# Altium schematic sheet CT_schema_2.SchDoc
size 461 x 297 mm
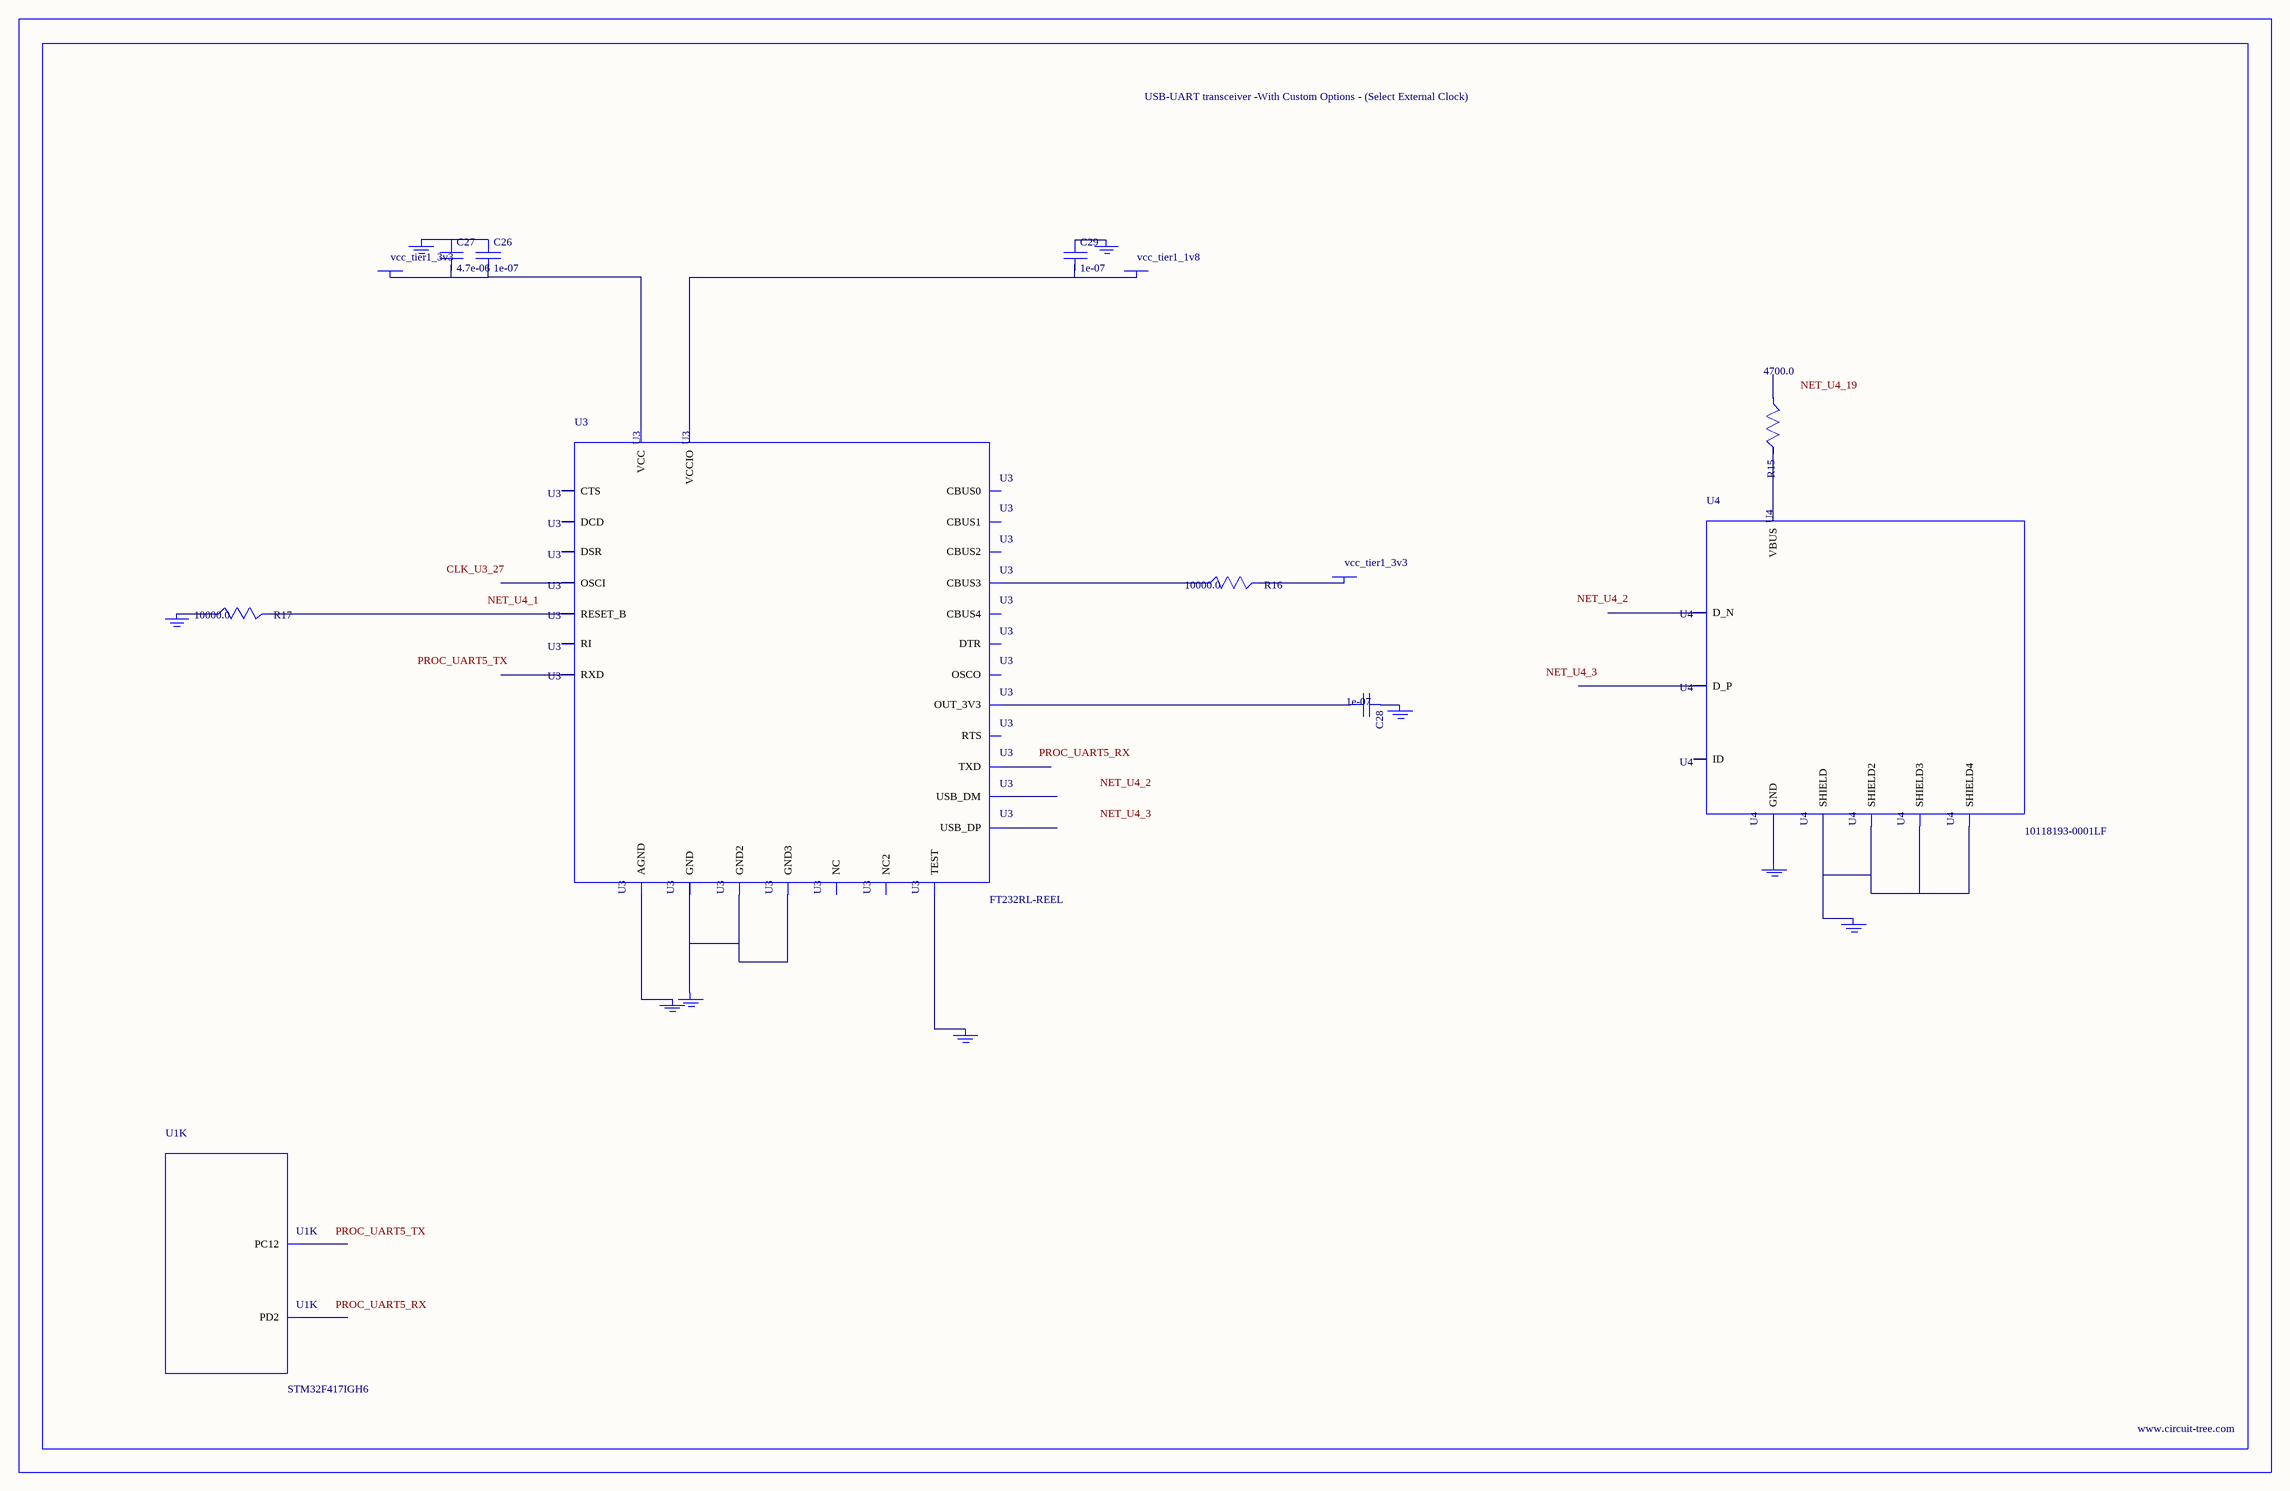
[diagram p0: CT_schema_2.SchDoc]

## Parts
BORDER1  (no value)
C26  1e-07  [C0402]
C27  4.7e-06  [C0805]
C28  1e-07  [C0402]
C29  1e-07  [C0402]
GND_INSTANCE_1_0  (no value)
GND_INSTANCE_1_1  (no value)
GND_INSTANCE_1_2  (no value)
GND_INSTANCE_1_3  (no value)
GND_INSTANCE_1_4  (no value)
GND_INSTANCE_1_5  (no value)
GND_INSTANCE_1_6  (no value)
GND_INSTANCE_1_7  (no value)
GND_INSTANCE_1_8  (no value)
POWER_INSTANCE_1_0  vcc_tier1_1v8
POWER_INSTANCE_1_1  vcc_tier1_3v3
POWER_INSTANCE_1_2  vcc_tier1_3v3
R15  4700.0  [R0603]
R16  10000.0  [R0603]
R17  10000.0  [R0603]
U1  STM32F417IGH6  [UFBGA176_25]  (part K of 15)
U3  FT232RL-REEL  [SSOP-28]
U4  10118193-0001LF  [FCI_10118193-0001LF]

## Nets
NetC26_1: C26.1 C27.1 GND_INSTANCE_1_3.0(GND)
NetC26_2: C26.2 C27.2 POWER_INSTANCE_1_2.0(PWR) U3.20(VCC)
NetC28_1: C28.1 GND_INSTANCE_1_1.0(GND)
NetC28_2: C28.2 U3.17(OUT_3V3)
NetC29_1: C29.1 GND_INSTANCE_1_0.0(GND)
NetC29_2: C29.2 POWER_INSTANCE_1_0.0(PWR) U3.4(VCCIO)
NetGND_INSTANCE_1_2_0: GND_INSTANCE_1_2.0(GND) R17.1
NetGND_INSTANCE_1_4_0: GND_INSTANCE_1_4.0(GND) U3.25(AGND)
NetGND_INSTANCE_1_5_0: GND_INSTANCE_1_5.0(GND) U3.26(TEST)
NetGND_INSTANCE_1_6_0: GND_INSTANCE_1_6.0(GND) U3.7(GND) U3.18(GND2) U3.21(GND3)
NetGND_INSTANCE_1_7_0: GND_INSTANCE_1_7.0(GND) U4.6(SHIELD) U4.7(SHIELD2) U4.8(SHIELD3) U4.9(SHIELD4)
NetGND_INSTANCE_1_8_0: GND_INSTANCE_1_8.0(GND) U4.5(GND)
NetPOWER_INSTANCE_1_1_0: POWER_INSTANCE_1_1.0(PWR) R16.2
NetR15_2: R15.2 U4.1(VBUS)
NetR16_1: R16.1 U3.14(CBUS3)
NetR17_2: R17.2 U3.19(RESET_B)

Not connected (* = marked no-connect by the designer): R15 1; U1 A12(PC12) D12(PD2); U3 1(TXD) 2(DTR) 3(RTS) 5(RXD) 6(RI) 8(NC) 9(DSR) 10(DCD) 11(CTS) 12(CBUS4) 13(CBUS2) 15(USB_DP) 16(USB_DM) 22(CBUS1) 23(CBUS0) 24(NC2) 27(OSCI) 28(OSCO); U4 2(D_N) 3(D_P) 4(ID)

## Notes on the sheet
- Labels drawn without touching a wire or pin: CLK_U3_27, NET_U4_1, NET_U4_2, NET_U4_3, NET_U4_19, PROC_UART5_RX, PROC_UART5_TX

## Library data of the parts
BORDER1 = BORDER_PAGE1
C26 C28 C29 = C0402C104K3RACTU
C27 = C0805C475K4RACTU
GND_INSTANCE_1_0-GND_INSTANCE_1_8 = GND
POWER_INSTANCE_1_0-POWER_INSTANCE_1_2 = PWR
R15 = RC0603JR-074K7L
R16 R17 = RC0603JR-0710KL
